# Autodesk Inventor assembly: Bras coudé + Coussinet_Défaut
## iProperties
Shininess: 64.0
Length Units: 11269
Angle Units: 11279
Time Units: 11290
Mass Units: 11283
Length Display Precision: 3
Angle Display Precision: 2
Compacted: True
Created: 2006-11
Part Number: Bras coudé + Coussinet_Défaut
Document SubType Name: Assembly
Designer: profs_sti
Density: 0.0
Volumn: 0.0
Area: 0.0
PropertySet Name: Model Information
Control State: 0
Master: False
Checked Out: False
Author: profs_sti
